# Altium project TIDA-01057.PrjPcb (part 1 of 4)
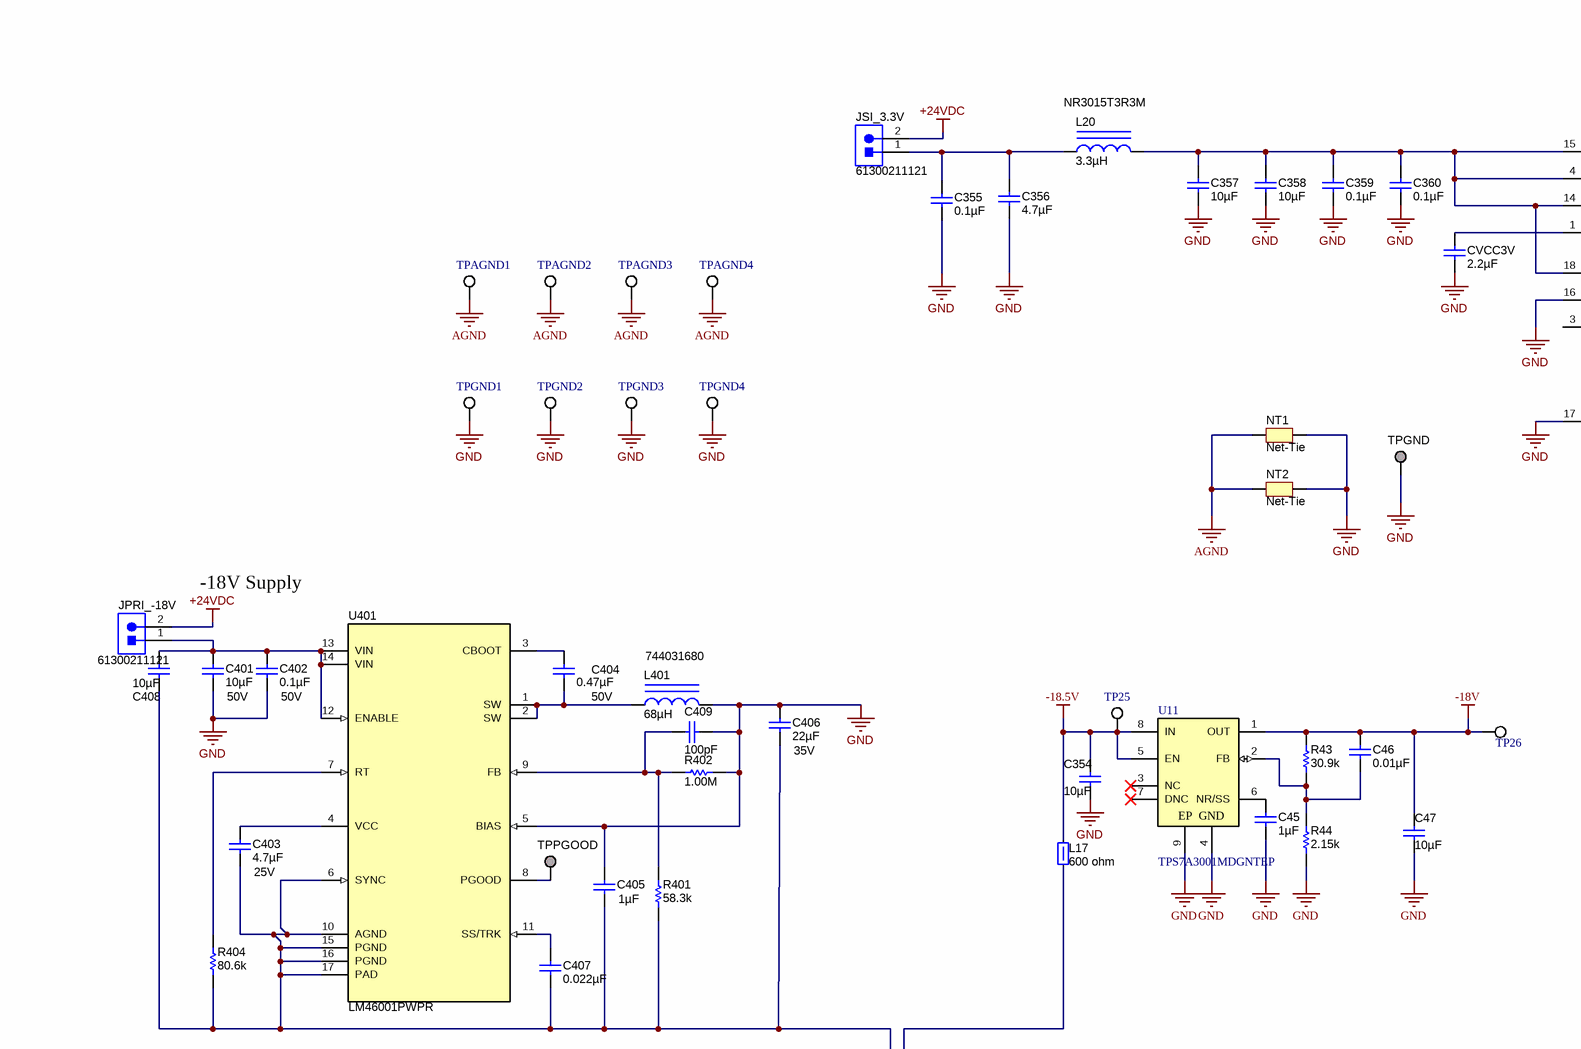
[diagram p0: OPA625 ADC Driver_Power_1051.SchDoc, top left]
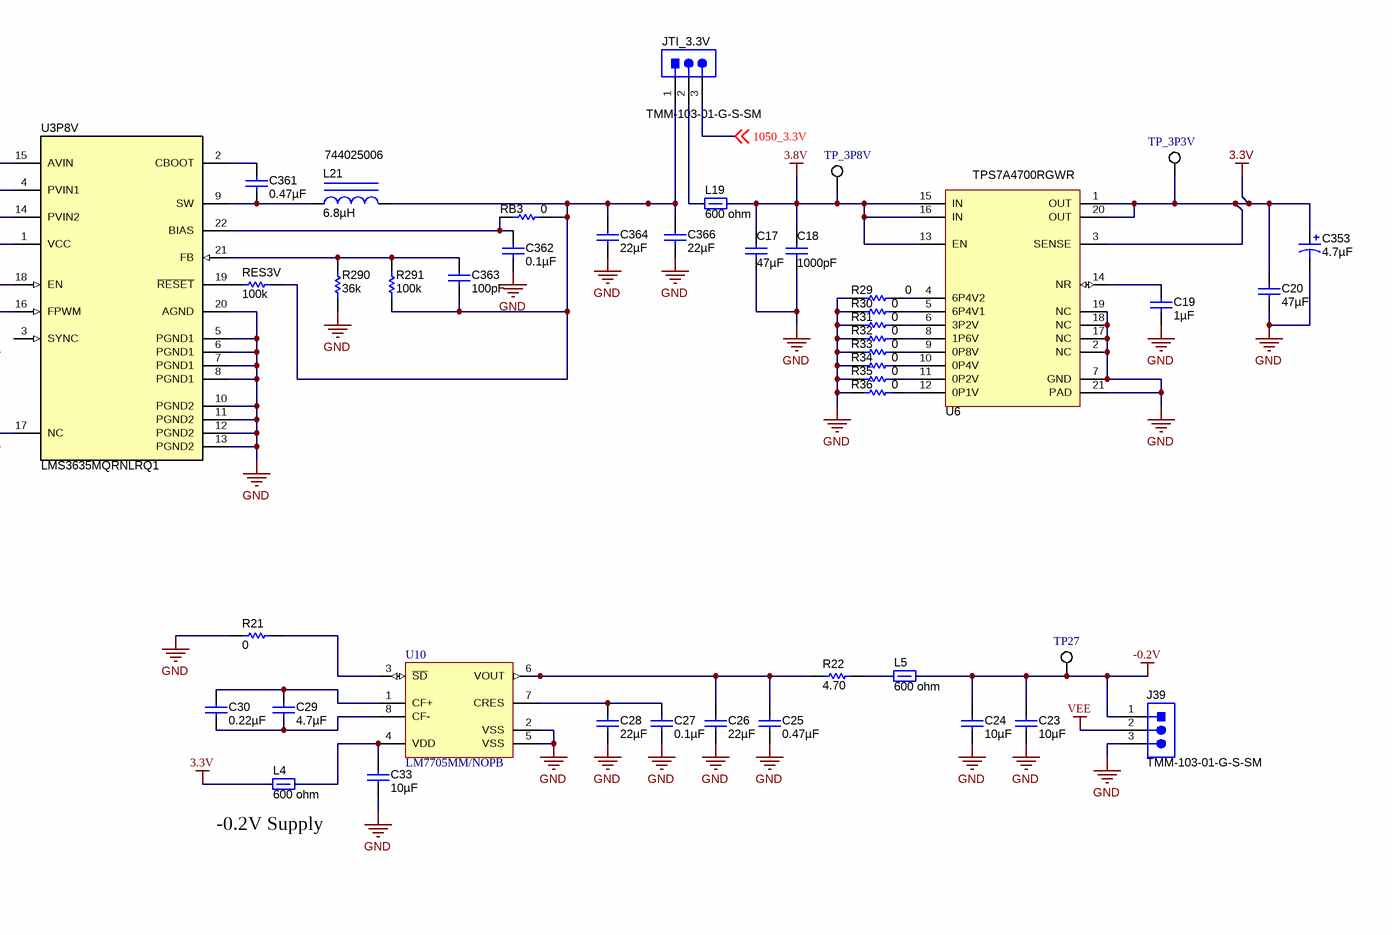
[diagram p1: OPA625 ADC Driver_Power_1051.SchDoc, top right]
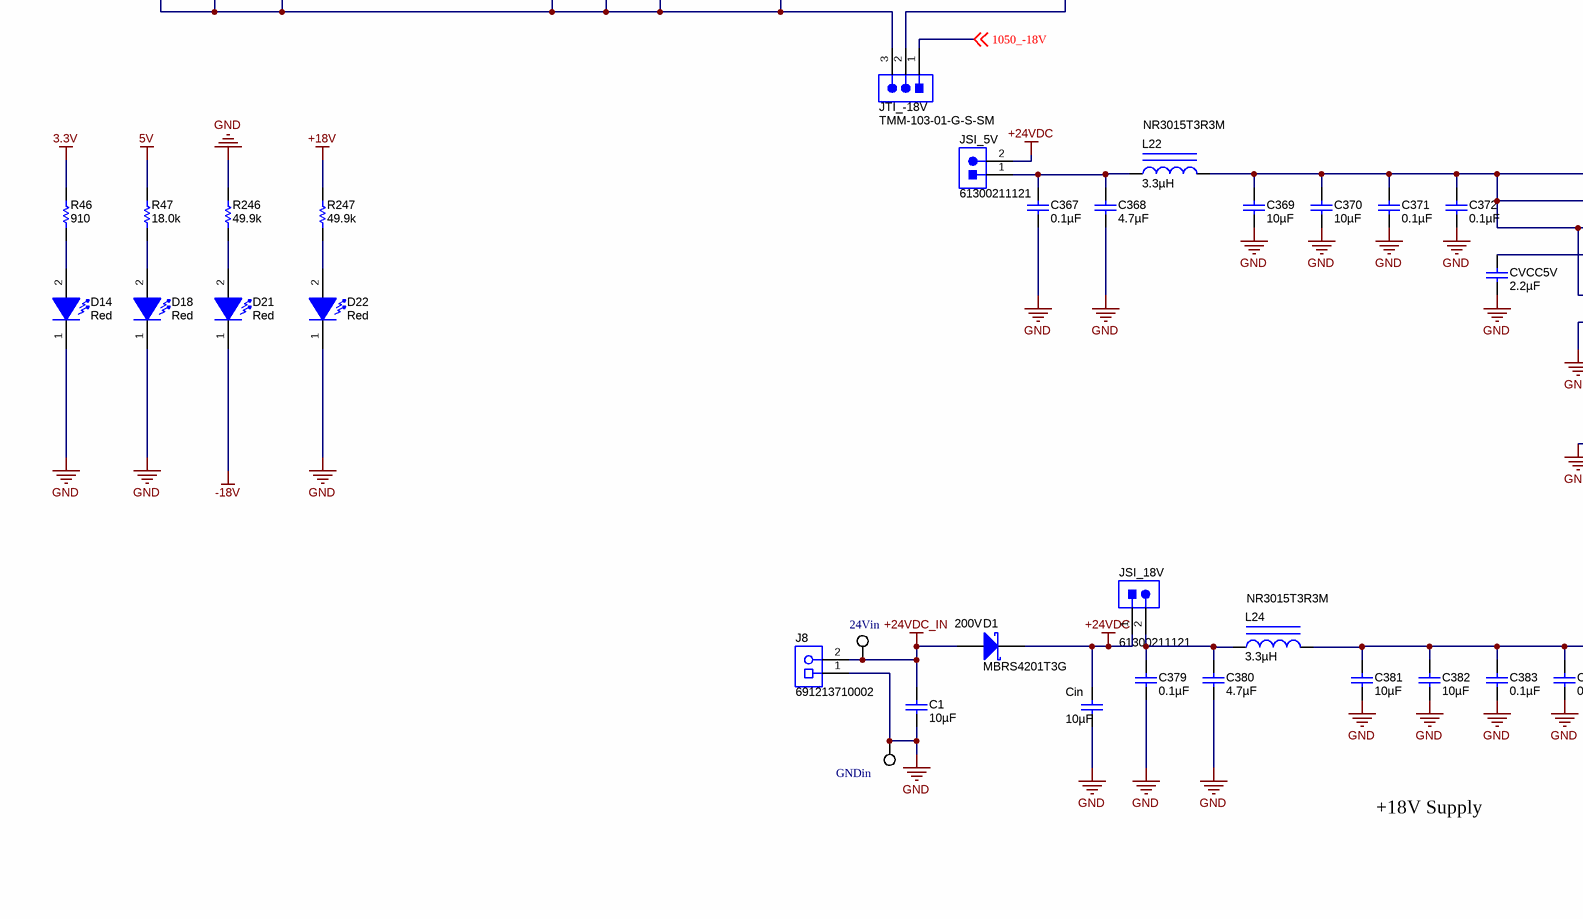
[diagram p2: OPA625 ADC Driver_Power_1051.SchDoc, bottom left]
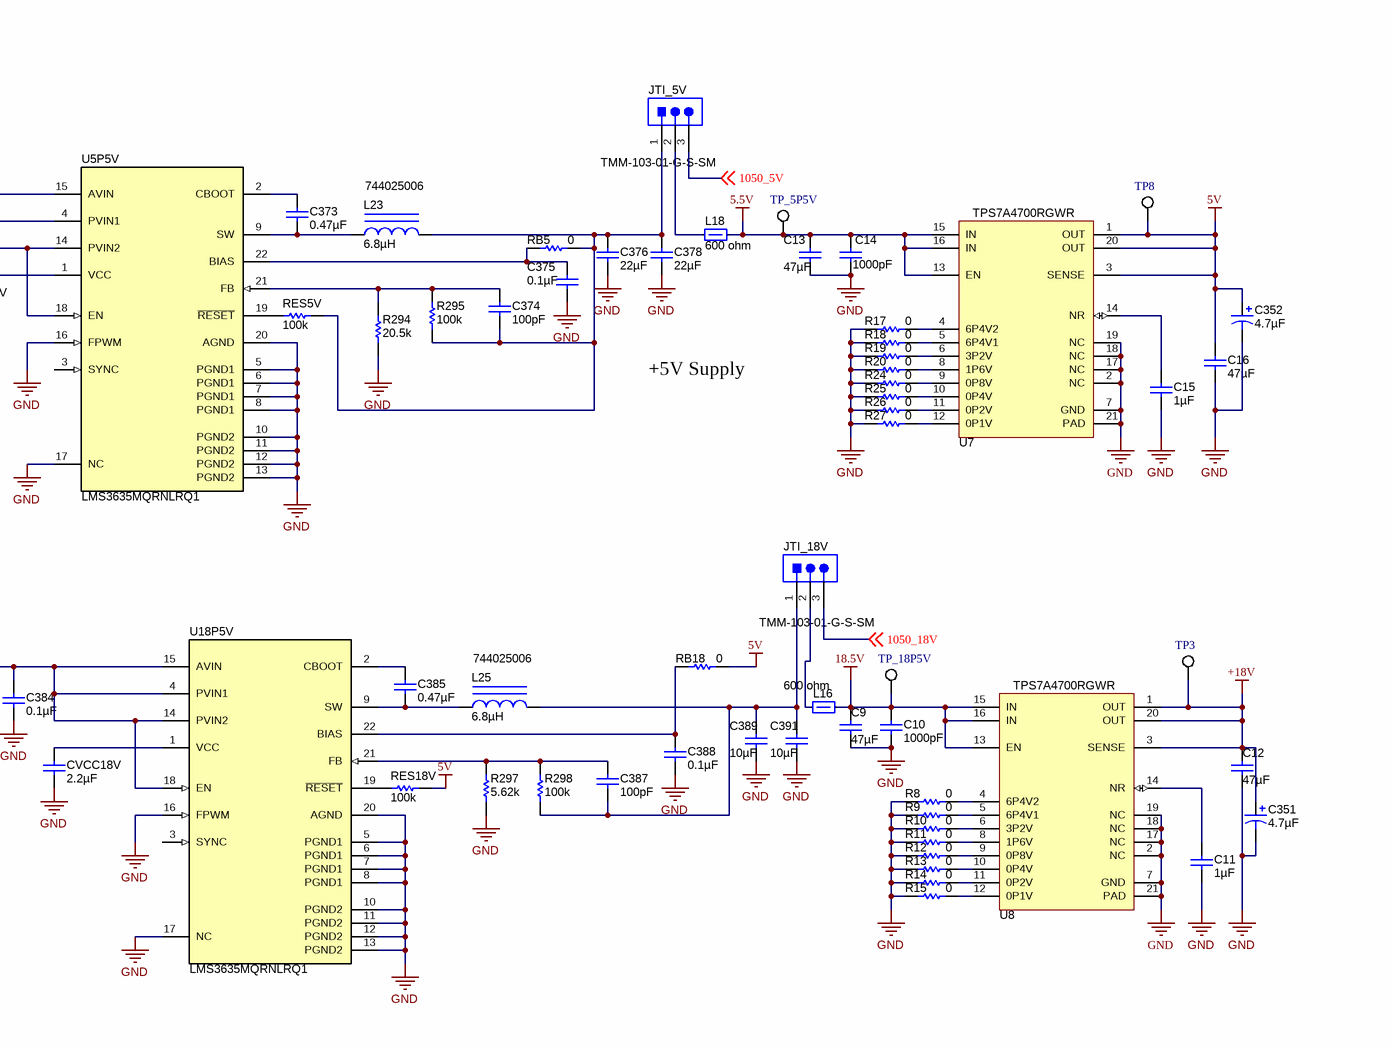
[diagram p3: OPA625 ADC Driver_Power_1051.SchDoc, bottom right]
CopyrightYear: 2017; EVM_Orderable: N/A; PCB_Layout: Dee Lim; PCB_Rev: E1; PRJ_Customer: Public Release; PRJ_Engineer: Taras Dudar & Shota Mago; PRJ_Number: TIDA-01057; PRJ_Title: OPA625 ADC Driver; SCH_Rev: E1; TechSupport: http://www.ti.com/support; TID: 01057
7 sheets, 538 parts. Net scope: global (net labels, ports and power ports of the same name join across sheets).
Board file: TIDA-01057.PcbDoc
Sheets:
  OPA625 ADC Driver_Power_1051.SchDoc
  OPA625 ADC Driver_Power_1050.SchDoc
  OPA625 ADC Driver_CoverSheet.SchDoc
  OPA625 ADC Driver_Connectors.SchDoc
  OPA625 ADC Driver_OPA625 ADC Driver REV1.0.SchDoc
  OPA625 ADC Driver_Clock.SchDoc
  OPA625 ADC Driver_Hardware.SchDoc

## Sheet OPA625 ADC Driver_Power_1051.SchDoc
size 558 x 431 mm; Date: Not shown in title block; ApprovedBy: Not shown in title block; CheckedBy: Not shown in title block; Author: Not shown in title block; CompanyName: Not shown in title block; Engineer: Not shown in title block; Organization: Not shown in title block; Address1: Not shown in title block; Address2: Not shown in title block; Address3: Not shown in title block; Address4: Not shown in title block; DocumentNumber: 2; Revision: Use project parameter SCH_Rev; SheetNumber: 2; SheetTotal: 8; PageSetup: Record=PageOptions¦CenterHorizontal=True¦CenterVertical=True¦PrintScale=0.62¦XCorrection=1.00¦YCorrection=1.00¦PrintKind=0¦BorderSize=5000000¦LeftOffset=0¦BottomOffset=0¦Orientation=2¦PaperLength=1000¦PaperWidth=1000¦Scale=100¦PaperSource=15¦PrintQuality=-3¦MediaType=1¦DitherType=10¦PrintScaleMode=1¦PaperKind=11x17¦PaperIndex=17

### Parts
24Vin  5015  [Testpoint_Keystone_Miniature]  (value not drawn)
C1  ValueDisplayed: 10µF  [1210_280]  (hidden comment: UMK325AB7106KM-T)
C9  ValueDisplayed: 47µF  [1206_190]  (hidden comment: C3216X5R1E476M160AC)
C10  ValueDisplayed: 1000pF  [0603]  (hidden comment: CGA3E2X7R2A102K080AA)
C11  ValueDisplayed: 1µF  [0805_HV]  (hidden comment: C2012X7S2A105K125AB)
C12  ValueDisplayed: 47µF  [1206_190]  (hidden comment: C3216X5R1E476M160AC)
C13  ValueDisplayed: 47µF  [1206_190]  (hidden comment: C3216X5R1E476M160AC)
C14  ValueDisplayed: 1000pF  [0603]  (hidden comment: GRM1885C1H102FA01J)
C15  ValueDisplayed: 1µF  [0603]  (hidden comment: GRM188R71E105KA12D)
C16  ValueDisplayed: 47µF  [1206_190]  (hidden comment: C3216X5R1E476M160AC)
C17  ValueDisplayed: 47µF  [1206_190]  (hidden comment: C3216X5R1E476M160AC)
C18  ValueDisplayed: 1000pF  [0603]  (hidden comment: GRM1885C1H102FA01J)
C19  ValueDisplayed: 1µF  [0603]  (hidden comment: GRM188R71E105KA12D)
C20  ValueDisplayed: 47µF  [1206_190]  (hidden comment: C3216X5R1E476M160AC)
C23  ValueDisplayed: 10µF  [0603]  (hidden comment: GRM188R61A106ME69D)
C24  ValueDisplayed: 10µF  [0603]  (hidden comment: GRM188R61A106ME69D)
C25  ValueDisplayed: 0.47µF  [0603]  (hidden comment: GRM188R71E474KA12D)
C26  ValueDisplayed: 22µF  [0603]  (hidden comment: GRM188R60J226MEA0D)
C27  ValueDisplayed: 0.1µF  [0603]  (hidden comment: GRM188R61C104KA01D)
C28  ValueDisplayed: 22µF  [0603]  (hidden comment: GRM188R60J226MEA0D)
C29  ValueDisplayed: 4.7µF  [0603]  (hidden comment: GRM188R61A475MAAJ)
C30  ValueDisplayed: 0.22µF  [0603]  (hidden comment: GRM188R61A224KA01D)
C33  ValueDisplayed: 10µF  [0603]  (hidden comment: GRM188R61A106ME69D)
C45  ValueDisplayed: 1µF  [0805_HV]  (hidden comment: C2012X7S2A105K125AB)
C46  ValueDisplayed: 0.01µF  [0603]  (hidden comment: GCM188R71H103KA37D)
C47  ValueDisplayed: 10µF  [1210_280]  (hidden comment: UMK325AB7106KM-T)
C351  ValueDisplayed: 4.7µF  [6032-28]  (hidden comment: 293D475X9025C2TE3)
C352  ValueDisplayed: 4.7µF  [6032-28]  (hidden comment: 293D475X9025C2TE3)
C353  ValueDisplayed: 4.7µF  [6032-28]  (hidden comment: 293D475X9025C2TE3)
C354  ValueDisplayed: 10µF  [1210_280]  (hidden comment: UMK325AB7106KM-T)
C355  ValueDisplayed: 0.1µF  [0805_HV]  (hidden comment: C2012X7R2A104K125AA)
C356  ValueDisplayed: 4.7µF  [1206]  (hidden comment: C3216X7R1V475K085AC)
C357  ValueDisplayed: 10µF  [1206_180]  (hidden comment: GRM31CR71E106KA12L)
C358  ValueDisplayed: 10µF  [1206_180]  (hidden comment: GRM31CR71E106KA12L)
C359  ValueDisplayed: 0.1µF  [0805_HV]  (hidden comment: C2012X7R2A104K125AA)
C360  ValueDisplayed: 0.1µF  [0805_HV]  (hidden comment: C2012X7R2A104K125AA)
C361  ValueDisplayed: 0.47µF  [0603]  (hidden comment: GCM188R71E474KA64D)
C362  ValueDisplayed: 0.1µF  [0402]  (hidden comment: C1005X6S1H104K050BB)
C363  ValueDisplayed: 100pF  [0402]  (hidden comment: C0402C101J3GACTU)
C364  ValueDisplayed: 22µF  [1210_280]  (hidden comment: CGA6P1X7R1C226M250AC)
C366  ValueDisplayed: 22µF  [1210_280]  (hidden comment: CGA6P1X7R1C226M250AC)
C367  ValueDisplayed: 0.1µF  [0805_HV]  (hidden comment: C2012X7R2A104K125AA)
C368  ValueDisplayed: 4.7µF  [1206]  (hidden comment: C3216X7R1V475K085AC)
C369  ValueDisplayed: 10µF  [1206_180]  (hidden comment: GRM31CR71E106KA12L)
C370  ValueDisplayed: 10µF  [1206_180]  (hidden comment: GRM31CR71E106KA12L)
C371  ValueDisplayed: 0.1µF  [0805_HV]  (hidden comment: C2012X7R2A104K125AA)
C372  ValueDisplayed: 0.1µF  [0805_HV]  (hidden comment: C2012X7R2A104K125AA)
C373  ValueDisplayed: 0.47µF  [0603]  (hidden comment: GCM188R71E474KA64D)
C374  ValueDisplayed: 100pF  [0402]  (hidden comment: C0402C101J3GACTU)
C375  ValueDisplayed: 0.1µF  [0402]  (hidden comment: C1005X6S1H104K050BB)
C376  ValueDisplayed: 22µF  [1210_280]  (hidden comment: CGA6P1X7R1C226M250AC)
C378  ValueDisplayed: 22µF  [1210_280]  (hidden comment: CGA6P1X7R1C226M250AC)
C379  ValueDisplayed: 0.1µF  [0805_HV]  (hidden comment: C2012X7R2A104K125AA)
C380  ValueDisplayed: 4.7µF  [1206]  (hidden comment: C3216X7R1V475K085AC)
C381  ValueDisplayed: 10µF  [1206_180]  (hidden comment: GRM31CR71E106KA12L)
C382  ValueDisplayed: 10µF  [1206_180]  (hidden comment: GRM31CR71E106KA12L)
C383  ValueDisplayed: 0.1µF  [0805_HV]  (hidden comment: C2012X7R2A104K125AA)
C384  ValueDisplayed: 0.1µF  [0805_HV]  (hidden comment: C2012X7R2A104K125AA)
C385  ValueDisplayed: 0.47µF  [0603]  (hidden comment: GCM188R71E474KA64D)
C387  ValueDisplayed: 100pF  [0402]  (hidden comment: C0402C101J3GACTU)
C388  ValueDisplayed: 0.1µF  [0402]  (hidden comment: C1005X6S1H104K050BB)
C389  ValueDisplayed: 10µF  [1210_280]  (hidden comment: UMK325AB7106KM-T)
C391  ValueDisplayed: 10µF  [1210_280]  (hidden comment: UMK325AB7106KM-T)
C401  ValueDisplayed: 10µF  Value2: 50V  [1210_280]  (hidden comment: C3225X7S1H106K250AB)
C402  ValueDisplayed: 0.1µF  Value2: 50V  [0603]  (hidden comment: C1608X5R1H104K080AA)
C403  ValueDisplayed: 4.7µF  Value2: 25V  [0603]  (hidden comment: GRM188R61E475KE11D)
C404  ValueDisplayed: 0.47µF  Value2: 50V  [0603]  (hidden comment: C1608X5R1H474K080AB)
C405  ValueDisplayed: 1µF  [0603]  (hidden comment: C1608X7R1V105K080AC)
C406  ValueDisplayed: 22µF  Value2: 35V  [1206_180]  (hidden comment: C3216X5R1V226M160AC)
C407  ValueDisplayed: 0.022µF  [0603]  (hidden comment: C0603C223K3RACTU)
C408  ValueDisplayed: 10µF  [1210_280]  (hidden comment: UMK325AB7106KM-T)
C409  ValueDisplayed: 100pF  [0603]  (hidden comment: 885012006057)
Cin  ValueDisplayed: 10µF  [1210_280]  (hidden comment: UMK325AB7106KM-T)
CVCC3V  ValueDisplayed: 2.2µF  [0603]  (hidden comment: GCM188R70J225KE22D)
CVCC5V  ValueDisplayed: 2.2µF  [0603]  (hidden comment: GCM188R70J225KE22D)
CVCC18V  ValueDisplayed: 2.2µF  [0603]  (hidden comment: GCM188R70J225KE22D)
D1  MBRS4201T3G  value 200V  [SMC]
D14  value Red  [WL-SMCW_RED]  (hidden comment: 150060RS75000)
D18  value Red  [WL-SMCW_RED]  (hidden comment: 150060RS75000)
D21  value Red  [WL-SMCW_RED]  (hidden comment: 150060RS75000)
D22  value Red  [WL-SMCW_RED]  (hidden comment: 150060RS75000)
GNDin  5015  [Testpoint_Keystone_Miniature]  (value not drawn)
J8  691213710002  [Wurth_691213710002]
J39  TMM-103-01-G-S-SM  [Samtec_TMM-103-01-x-S-SM]
JPRI_-18V  61300211121  [WURTH_61300211121]
JSI_3.3V  61300211121  [WURTH_61300211121]
JSI_5V  61300211121  [WURTH_61300211121]
JSI_18V  61300211121  [WURTH_61300211121]
JTI_3.3V  TMM-103-01-G-S-SM  [Samtec_TMM-103-01-x-S-SM]
JTI_5V  TMM-103-01-G-S-SM  [Samtec_TMM-103-01-x-S-SM]
JTI_18V  TMM-103-01-G-S-SM  [Samtec_TMM-103-01-x-S-SM]
JTI_-18V  TMM-103-01-G-S-SM  [Samtec_TMM-103-01-x-S-SM]
L4  value 600 ohm  [0805_HV]  (hidden comment: MPZ2012S601A)
L5  value 600 ohm  [0805_HV]  (hidden comment: MPZ2012S601A)
L16  value 600 ohm  [0805_HV]  (hidden comment: MPZ2012S601A)
L17  value 600 ohm  [0805_HV]  (hidden comment: MPZ2012S601A)
L18  value 600 ohm  [0805_HV]  (hidden comment: MPZ2012S601A)
L19  value 600 ohm  [0805_HV]  (hidden comment: MPZ2012S601A)
L20  NR3015T3R3M  ValueDisplayed: 3.3µH  [NR3015]
L21  744025006  ValueDisplayed: 6.8µH  [WE-TPC_2828]
L22  NR3015T3R3M  ValueDisplayed: 3.3µH  [NR3015]
L23  744025006  ValueDisplayed: 6.8µH  [WE-TPC_2828]
L24  NR3015T3R3M  ValueDisplayed: 3.3µH  [NR3015]
L25  744025006  ValueDisplayed: 6.8µH  [WE-TPC_2828]
L401  744031680  ValueDisplayed: 68µH  [WE-TPC_3816]
NT1  Net-Tie  [Net-Tie_50milWide_30milLong]  (net tie, no BOM)
NT2  Net-Tie  [Net-Tie_50milWide_30milLong]  (net tie, no BOM)
R8  ValueDisplayed: 0  [0402]  (hidden comment: ERJ-2GE0R00X)
R9  ValueDisplayed: 0  [0402]  (hidden comment: ERJ-2GE0R00X)
R10  ValueDisplayed: 0  [0402]  (hidden comment: ERJ-2GE0R00X)
R11  ValueDisplayed: 0  [0402]  (hidden comment: ERJ-2GE0R00X)
R12  ValueDisplayed: 0  [0402]  (hidden comment: ERJ-2GE0R00X)
R13  ValueDisplayed: 0  [0402]  (hidden comment: ERJ-2GE0R00X)
R14  ValueDisplayed: 0  [0402]  (hidden comment: ERJ-2GE0R00X)
R15  ValueDisplayed: 0  [0402]  (hidden comment: ERJ-2GE0R00X)
R17  ValueDisplayed: 0  [0402]  (hidden comment: ERJ-2GE0R00X)
R18  ValueDisplayed: 0  [0402]  (hidden comment: ERJ-2GE0R00X)
R19  ValueDisplayed: 0  [0402]  (hidden comment: ERJ-2GE0R00X)
R20  ValueDisplayed: 0  [0402]  (hidden comment: ERJ-2GE0R00X)
R21  ValueDisplayed: 0  [0603]  (hidden comment: CRCW06030000Z0EA)
R22  ValueDisplayed: 4.70  [0603]  (hidden comment: RT0603DRE074R7L)
R24  ValueDisplayed: 0  [0402]  (hidden comment: ERJ-2GE0R00X)
R25  ValueDisplayed: 0  [0402]  (hidden comment: ERJ-2GE0R00X)
R26  ValueDisplayed: 0  [0402]  (hidden comment: ERJ-2GE0R00X)
R27  ValueDisplayed: 0  [0402]  (hidden comment: ERJ-2GE0R00X)
R29  ValueDisplayed: 0  [0402]  (hidden comment: ERJ-2GE0R00X)
R30  ValueDisplayed: 0  [0402]  (hidden comment: ERJ-2GE0R00X)
R31  ValueDisplayed: 0  [0402]  (hidden comment: ERJ-2GE0R00X)
R32  ValueDisplayed: 0  [0402]  (hidden comment: ERJ-2GE0R00X)
R33  ValueDisplayed: 0  [0402]  (hidden comment: ERJ-2GE0R00X)
R34  ValueDisplayed: 0  [0402]  (hidden comment: ERJ-2GE0R00X)
R35  ValueDisplayed: 0  [0402]  (hidden comment: ERJ-2GE0R00X)
R36  ValueDisplayed: 0  [0402]  (hidden comment: ERJ-2GE0R00X)
R43  ValueDisplayed: 30.9k  [0603]  (hidden comment: RG1608P-3092-B-T5)
R44  ValueDisplayed: 2.15k  [0603]  (hidden comment: RT0603BRD072K15L)
R46  ValueDisplayed: 910  [0603]  (hidden comment: RC0603JR-07910RL)
R47  ValueDisplayed: 18.0k  [0603]  (hidden comment: RT0603BRD0718KL)
R246  ValueDisplayed: 49.9k  [0603]  (hidden comment: RG1608P-4992-B-T5)
R247  ValueDisplayed: 49.9k  [0603]  (hidden comment: RG1608P-4992-B-T5)
R290  ValueDisplayed: 36k  [0402]  (hidden comment: CRCW040236K0JNED)
R291  ValueDisplayed: 100k  [0402]  (hidden comment: CRCW0402100KFKED)
R294  ValueDisplayed: 20.5k  [0402]  (hidden comment: CRCW040222K6FKED)
R295  ValueDisplayed: 100k  [0402]  (hidden comment: CRCW0402100KFKED)
R297  ValueDisplayed: 5.62k  [0402]  (hidden comment: PCF0402-12-5K62BT1)
R298  ValueDisplayed: 100k  [0402]  (hidden comment: CRCW0402100KFKED)
R401  ValueDisplayed: 58.3k  [0603]  (hidden comment: RT0603BRD0758K3L)
R402  ValueDisplayed: 1.00M  [0603]  (hidden comment: RC0603FR-071ML)
R404  ValueDisplayed: 80.6k  [0603]  (hidden comment: CRCW060380K6FKEA)
RB3  ValueDisplayed: 0  [0402]  (hidden comment: ERJ-2GE0R00X)
RB5  ValueDisplayed: 0  [0402]  (hidden comment: ERJ-2GE0R00X)
RB18  ValueDisplayed: 0  [0402]  (hidden comment: ERJ-2GE0R00X)
RES3V  ValueDisplayed: 100k  [0603]  (hidden comment: RG1608P-104-B-T5)
RES5V  ValueDisplayed: 100k  [0603]  (hidden comment: RG1608P-104-B-T5)
RES18V  ValueDisplayed: 100k  [0603]  (hidden comment: RG1608P-104-B-T5)
TP3  5015  [Testpoint_Keystone_Miniature]  (value not drawn)
TP8  5015  [Testpoint_Keystone_Miniature]  (value not drawn)
TP25  5015  [Testpoint_Keystone_Miniature]  (value not drawn)
TP26  5015  [Testpoint_Keystone_Miniature]  (value not drawn)
TP27  5015  [Testpoint_Keystone_Miniature]  (value not drawn)
TP_3P3V  5015  [Testpoint_Keystone_Miniature]  (value not drawn)
TP_3P8V  5015  [Testpoint_Keystone_Miniature]  (value not drawn)
TP_5P5V  5015  [Testpoint_Keystone_Miniature]  (value not drawn)
TP_18P5V  5015  [Testpoint_Keystone_Miniature]  (value not drawn)
TPAGND1  5015  [Testpoint_Keystone_Miniature]  (value not drawn)
TPAGND2  5015  [Testpoint_Keystone_Miniature]  (value not drawn)
TPAGND3  5015  [Testpoint_Keystone_Miniature]  (value not drawn)
TPAGND4  5015  [Testpoint_Keystone_Miniature]  (value not drawn)
TPGND  Pogo Pad  [PogoPad]  (value not drawn)  (no BOM)
TPGND1  5015  [Testpoint_Keystone_Miniature]  (value not drawn)
TPGND2  5015  [Testpoint_Keystone_Miniature]  (value not drawn)
TPGND3  5015  [Testpoint_Keystone_Miniature]  (value not drawn)
TPGND4  5015  [Testpoint_Keystone_Miniature]  (value not drawn)
TPPGOOD  Pogo Pad  [PogoPad]  (value not drawn)  (no BOM)
U3P8V  LMS3635MQRNLRQ1  [RNL0022A_NV]
U5P5V  LMS3635MQRNLRQ1  [RNL0022A_NV]
U6  TPS7A4700RGWR  [RGW0020A]
U7  TPS7A4700RGWR  [RGW0020A]
U8  TPS7A4700RGWR  [RGW0020A]
U10  LM7705MM/NOPB  [MUA08A_N]
U11  TPS7A3001MDGNTEP  [DGN0008D_N]
U18P5V  LMS3635MQRNLRQ1  [RNL0022A_NV]
U401  LM46001PWPR  [PWP0016G_N]

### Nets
3.3V: C20.1 C353.1(+) L4.2 R46.2 TP_3P3V.1 U6.1(OUT) U6.3(SENSE) U6.20(OUT)
3.8V: C17.1 C18.1 L19.2 TP_3P8V.1 U6.13(EN) U6.15(IN) U6.16(IN)
5.5V: C13.1 C14.1 L18.2 TP_5P5V.1 U7.13(EN) U7.15(IN) U7.16(IN)
5V: C16.1 C352.1(+) R47.2 RB18.2 RES18V.1 TP8.1 U7.1(OUT) U7.3(SENSE) U7.20(OUT)
18.5V: C9.1 C10.1 L16.1 TP_18P5V.1 U8.13(EN) U8.15(IN) U8.16(IN)
+18V: C12.1 C351.1(+) R247.2 TP3.1 U8.1(OUT) U8.3(SENSE) U8.20(OUT)
+24VDC: Cin.1 D1.1(K) JPRI_-18V.2 JSI_3.3V.2 JSI_5V.2 JSI_18V.1
+24VDC_IN: 24Vin.1 C1.1 D1.2(A) J8.2
-0.2V: C23.1 C24.1 J39.1 L5.1 TP27.1
-18.5V: C354.1 L17.1 TP25.1 U11.5(EN) U11.8(IN)
-18V: C46.1 C47.1 D21.1(K) R43.2 TP26.1 U11.1(OUT)
AGND: NT1.1 NT2.1 TPAGND1.1 TPAGND2.1 TPAGND3.1 TPAGND4.1
GND: C1.2 C9.2 C10.2 C11.2 C12.2 C13.2 C14.2 C15.1 C16.2 C17.2 C18.2 C19.1 C20.2 C23.2 C24.2 C25.2 C26.2 C27.2 C28.2 C33.2 C45.2 C47.2 C351.2(-) C352.2(-) C353.2(-) C354.2 C355.2 C356.2 C357.2 C358.2 C359.2 C360.2 C362.2 C364.2 C366.2 C367.2 C368.2 C369.2 C370.2 C371.2 C372.2 C375.2 C376.2 C378.2 C379.2 C380.2 C381.2 C382.2 C383.2 C384.2 C388.2 C389.2 C391.2 C401.2 C402.2 C405.1 C406.1 C409.1 Cin.2 CVCC3V.2 CVCC5V.2 CVCC18V.2 D14.1(K) D18.1(K) D22.1(K) GNDin.1 J8.1 J39.3 L401.2 NT1.2 NT2.2 R8.1 R9.1 R10.1 R11.1 R12.1 R13.1 R14.1 R15.1 R17.1 R18.1 R19.1 R20.1 R21.1 R24.1 R25.1 R26.1 R27.1 R29.1 R30.1 R31.1 R32.1 R33.1 R34.1 R35.1 R36.1 R44.1 R246.2 R290.1 R294.1 R297.1 R402.2 TPGND.1 TPGND1.1 TPGND2.1 TPGND3.1 TPGND4.1 U3P8V.5(PGND1) U3P8V.6(PGND1) U3P8V.7(PGND1) U3P8V.8(PGND1) U3P8V.10(PGND2) U3P8V.11(PGND2) U3P8V.12(PGND2) U3P8V.13(PGND2) U3P8V.16(FPWM) U3P8V.17(NC) U3P8V.20(AGND) U5P5V.5(PGND1) U5P5V.6(PGND1) U5P5V.7(PGND1) U5P5V.8(PGND1) U5P5V.10(PGND2) U5P5V.11(PGND2) U5P5V.12(PGND2) U5P5V.13(PGND2) U5P5V.16(FPWM) U5P5V.17(NC) U5P5V.20(AGND) U6.2(NC) U6.7(GND) U6.17(NC) U6.18(NC) U6.19(NC) U6.21(PAD) U7.2(NC) U7.7(GND) U7.17(NC) U7.18(NC) U7.19(NC) U7.21(PAD) U8.2(NC) U8.7(GND) U8.17(NC) U8.18(NC) U8.19(NC) U8.21(PAD) U10.2(VSS) U10.5(VSS) U11.4(GND) U11.9(EP) U18P5V.5(PGND1) U18P5V.6(PGND1) U18P5V.7(PGND1) U18P5V.8(PGND1) U18P5V.10(PGND2) U18P5V.11(PGND2) U18P5V.12(PGND2) U18P5V.13(PGND2) U18P5V.16(FPWM) U18P5V.17(NC) U18P5V.20(AGND) U401.5(BIAS)
VEE: J39.2
1050_3.3V: JTI_3.3V.3 ; off-sheet 1050_3.3V
1050_5V: JTI_5V.3 ; off-sheet 1050_5V
1050_18V: JTI_18V.3 ; off-sheet 1050_18V
1050_-18V: JTI_-18V.1 ; off-sheet 1050_-18V
NetC11_1: C11.1 U8.14(NR)
NetC15_2: C15.2 U7.14(NR)
NetC19_2: C19.2 U6.14(NR)
NetC25_1: C25.1 C26.1 R22.1 U10.6(VOUT)
NetC27_1: C27.1 C28.1 U10.7(CRES)
NetC29_1: C29.1 C30.1 U10.1(CF+)
NetC29_2: C29.2 C30.2 U10.8(CF-)
NetC33_1: C33.1 L4.1 U10.4(VDD)
NetC45_1: C45.1 U11.6(NR/SS)
NetC46_2: C46.2 R43.1 R44.2 U11.2(FB)
NetC355_1: C355.1 C356.1 JSI_3.3V.1 L20.1
NetC357_1: C357.1 C358.1 C359.1 C360.1 L20.2 U3P8V.4(PVIN1) U3P8V.14(PVIN2) U3P8V.15(AVIN) U3P8V.18(EN)
NetC361_1: C361.1 U3P8V.2(CBOOT)
NetC361_2: C361.2 L21.1 U3P8V.9(SW)
NetC362_1: C362.1 RB3.1 U3P8V.22(BIAS)
NetC363_1: C363.1 R290.2 R291.2 U3P8V.21(FB)
NetC363_2: C363.2 C364.1 C366.1 JTI_3.3V.1 L21.2 R291.1 RB3.2 RES3V.1
NetC367_1: C367.1 C368.1 JSI_5V.1 L22.1
NetC369_1: C369.1 C370.1 C371.1 C372.1 L22.2 U5P5V.4(PVIN1) U5P5V.14(PVIN2) U5P5V.15(AVIN) U5P5V.18(EN)
NetC373_1: C373.1 U5P5V.2(CBOOT)
NetC373_2: C373.2 L23.1 U5P5V.9(SW)
NetC374_1: C374.1 R294.2 R295.2 U5P5V.21(FB)
NetC374_2: C374.2 C376.1 C378.1 JTI_5V.1 L23.2 R295.1 RB5.2 RES5V.1
NetC375_1: C375.1 RB5.1 U5P5V.22(BIAS)
NetC379_1: C379.1 C380.1 JSI_18V.2 L24.1
NetC381_1: C381.1 C382.1 C383.1 C384.1 L24.2 U18P5V.4(PVIN1) U18P5V.14(PVIN2) U18P5V.15(AVIN) U18P5V.18(EN)
NetC385_1: C385.1 U18P5V.2(CBOOT)
NetC385_2: C385.2 L25.1 U18P5V.9(SW)
NetC387_1: C387.1 R297.2 R298.2 U18P5V.21(FB)
NetC387_2: C387.2 C389.1 C391.1 JTI_18V.1 L25.2 R298.1
NetC388_1: C388.1 RB18.1 U18P5V.22(BIAS)
NetC401_1: C401.1 C402.1 C408.1 JPRI_-18V.1 U401.12(ENABLE) U401.13(VIN) U401.14(VIN)
NetC403_1: C403.1 U401.4(VCC)
NetC403_2: C403.2 C405.2 C406.2 C407.2 C408.2 JTI_-18V.3 R401.1 R404.1 U401.6(SYNC) U401.10(AGND) U401.15(PGND) U401.16(PGND) U401.17(PAD)
NetC404_1: C404.1 U401.3(CBOOT)
NetC404_2: C404.2 L401.1 U401.1(SW) U401.2(SW)
NetC407_1: C407.1 U401.11(SS/TRK)
NetC409_2: C409.2 R401.2 R402.1 U401.9(FB)
NetCVCC3V_1: CVCC3V.1 U3P8V.1(VCC)
NetCVCC5V_1: CVCC5V.1 U5P5V.1(VCC)
NetCVCC18V_1: CVCC18V.1 U18P5V.1(VCC)
NetD14_2: D14.2(A) R46.1
NetD18_2: D18.2(A) R47.1
NetD21_2: D21.2(A) R246.1
NetD22_2: D22.2(A) R247.1
NetJTI_3.3V_2: JTI_3.3V.2 L19.1
NetJTI_5V_2: JTI_5V.2 L18.1
NetJTI_18V_2: JTI_18V.2 L16.2
NetJTI_-18V_2: JTI_-18V.2 L17.2
NetL5_2: L5.2 R22.2
NetR8_2: R8.2 U8.4(6P4V2)
NetR9_2: R9.2 U8.5(6P4V1)
NetR10_2: R10.2 U8.6(3P2V)
NetR11_2: R11.2 U8.8(1P6V)
NetR12_2: R12.2 U8.9(0P8V)
NetR13_2: R13.2 U8.10(0P4V)
NetR14_2: R14.2 U8.11(0P2V)
NetR15_2: R15.2 U8.12(0P1V)
NetR17_2: R17.2 U7.4(6P4V2)
NetR18_2: R18.2 U7.5(6P4V1)
NetR19_2: R19.2 U7.6(3P2V)
NetR20_2: R20.2 U7.8(1P6V)
NetR21_2: R21.2 U10.3(~{SD})
NetR24_2: R24.2 U7.9(0P8V)
NetR25_2: R25.2 U7.10(0P4V)
NetR26_2: R26.2 U7.11(0P2V)
NetR27_2: R27.2 U7.12(0P1V)
NetR29_2: R29.2 U6.4(6P4V2)
NetR30_2: R30.2 U6.5(6P4V1)
NetR31_2: R31.2 U6.6(3P2V)
NetR32_2: R32.2 U6.8(1P6V)
NetR33_2: R33.2 U6.9(0P8V)
NetR34_2: R34.2 U6.10(0P4V)
NetR35_2: R35.2 U6.11(0P2V)
NetR36_2: R36.2 U6.12(0P1V)
NetR404_2: R404.2 U401.7(RT)
NetRES3V_2: RES3V.2 U3P8V.19(~{RESET})
NetRES5V_2: RES5V.2 U5P5V.19(~{RESET})
NetRES18V_2: RES18V.2 U18P5V.19(~{RESET})
NetTPPGOOD_1: TPPGOOD.1 U401.8(PGOOD)

Not connected (* = marked no-connect by the designer): U3P8V 3(SYNC); U5P5V 3(SYNC); U11 3(NC)* 7(DNC)*; U18P5V 3(SYNC)

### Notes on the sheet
- -18V Supply
- (near L4) -0.2V Supply
- +5V Supply
- +18V Supply

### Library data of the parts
24Vin GNDin TP3 TP8 TP25-TP27 TP_3P3V TP_3P8V TP_5P5V TP_18P5V TPAGND1-TPAGND4 TPGND1-TPGND4 = 5015: Test Point, Miniature, SMT; Manufacturer: Keystone; CompType: Test Point Loop
C1 = UMK325AB7106KM-T: CAP, CERM, 10 µF, 50 V, +/- 10%, X7R, 1210; Manufacturer: Taiyo Yuden; Polarized: N; CompType: Capacitor; Value: 10uF; U/M: EA; Cap_F: 0.00001; Tolerance_%: 10; Value1: Unknown; VDC_V: 50; Value2: 50V; TaMin_C: -55; TaMax_C: 125; Cap_Case: 1210; SizeArea_mm2: 8; SizeAreaWB_mm2: 14.7; SizeX_mm: 3.2; SizeY_mm: 2.5; SizeZ_mm: 2.8; AEC Category: Q200
C9 C12 C13 C16 C17 C20 = C3216X5R1E476M160AC: CAP, CERM, 47 µF, 25 V, +/- 20%, X5R, 1206_190; Manufacturer: TDK; Polarized: N; CompType: Capacitor; Value: 47uF; U/M: EA; Cap_F: 0.000047; Tolerance_%: 20; Value1: Unknown; VDC_V: 25; Value2: 25V; TaMin_C: -55; TaMax_C: 85; Cap_Case: 1206; AEC Category: Q200
C10 = CGA3E2X7R2A102K080AA: CAP, CERM, 1000 pF, 100 V, +/- 10%, X7R, AEC-Q200 Grade 1, 0603; Manufacturer: TDK; Polarized: N; CompType: Capacitor; Value: 1000pF; U/M: EA; Cap_F: 0.000000001; Tolerance_%: 10; ESR_ohm: 1.97137; Value1: 1.97137 ohm; VDC_V: 100; Value2: 100V; IRMS_A: 0.305705; TaMin_C: -55; TaMax_C: 125; SizeArea_mm2: 1.28; SizeAreaWB_mm2: 4.68; SizeX_mm: 1.6; SizeY_mm: 0.8; SizeZ_mm: 1; AEC Category: Q200; AEC Qualified: Y
C11 C45 = C2012X7S2A105K125AB: CAP, CERM, 1 µF, 100 V, +/- 10%, X7S, 0805; Manufacturer: TDK; Polarized: N; CompType: Capacitor; Value: 1uF; U/M: EA; Cap_F: 0.000001; Tolerance_%: 10; ESR_ohm: 0.008255; Value1: 0.008255 ohm; VDC_V: 100; Value2: 100V; IRMS_A: 2.27442; TaMin_C: -55; TaMax_C: 125; Cap_Case: 0805; SizeArea_mm2: 2.5; SizeAreaWB_mm2: 6.75; SizeX_mm: 2; SizeY_mm: 1.25; SizeZ_mm: 1.45; AEC Category: Q200
C14 C18 = GRM1885C1H102FA01J: CAP, CERM, 1000 pF, 50 V, +/- 1%, C0G/NP0, 0603; Manufacturer: MuRata; Polarized: N; CompType: Capacitor; Value: 1000pF; U/M: EA; Cap_F: 0.000000001; Tolerance_%: 1; Value1: Unknown; VDC_V: 50; Value2: 50V; TaMin_C: -55; TaMax_C: 125; AEC Category: Q200
C15 C19 = GRM188R71E105KA12D: CAP, CERM, 1 µF, 25 V, +/- 10%, X7R, 0603; Manufacturer: MuRata; Polarized: N; CompType: Capacitor; Value: 1uF; U/M: EA; Cap_F: 0.000001; Tolerance_%: 10; Value1: Unknown; VDC_V: 25; Value2: 25V; TaMin_C: -55; TaMax_C: 125; AEC Category: Q200
C23 C24 C33 = GRM188R61A106ME69D: CAP, CERM, 10 µF, 10 V, +/- 20%, X5R, 0603; Manufacturer: MuRata; Polarized: N; CompType: Capacitor; Value: 10uF; U/M: EA; Cap_F: 0.00001; Tolerance_%: 20; Value1: Unknown; VDC_V: 10; Value2: 10V; TaMin_C: -55; TaMax_C: 85; SizeArea_mm2: 1.28; SizeAreaWB_mm2: 4.68; SizeX_mm: 1.6; SizeY_mm: 0.8; SizeZ_mm: 1; AEC Category: Q200
C25 = GRM188R71E474KA12D: CAP, CERM, 0.47 µF, 25 V, +/- 10%, X7R, 0603; Manufacturer: MuRata; Polarized: N; CompType: Capacitor; Value: 0.47uF; U/M: EA; Cap_F: 0.00000047; Tolerance_%: 10; Value1: Unknown; VDC_V: 25; Value2: 25V; TaMin_C: -55; TaMax_C: 125; SizeArea_mm2: 1.28; SizeAreaWB_mm2: 4.68; SizeX_mm: 1.6; SizeY_mm: 0.8; SizeZ_mm: 1; AEC Category: Q200
C26 C28 = GRM188R60J226MEA0D: CAP, CERM, 22 µF, 6.3 V, +/- 20%, X5R, 0603; Manufacturer: MuRata; Polarized: N; CompType: Capacitor; Value: 22uF; U/M: EA; Cap_F: 0.000022; Tolerance_%: 20; Value1: Unknown; VDC_V: 6.3; Value2: 6.3V; TaMin_C: -55; TaMax_C: 85; SizeArea_mm2: 1.28; SizeAreaWB_mm2: 4.68; SizeX_mm: 1.6; SizeY_mm: 0.8; SizeZ_mm: 1; AEC Category: Q200
C27 = GRM188R61C104KA01D: CAP, CERM, 0.1 µF, 16 V, +/- 10%, X5R, 0603; Manufacturer: MuRata; Polarized: N; CompType: Capacitor; Value: 0.1uF; U/M: EA; Cap_F: 0.0000001; Tolerance_%: 10; Value1: Unknown; VDC_V: 16; Value2: 16V; TaMin_C: -55; TaMax_C: 85; SizeArea_mm2: 1.28; SizeAreaWB_mm2: 4.68; SizeX_mm: 1.6; SizeY_mm: 0.8; SizeZ_mm: 1; AEC Category: Q200
C29 = GRM188R61A475MAAJ: CAP, CERM, 4.7 µF, 10 V, +/- 20%, X5R, 0603; Manufacturer: MuRata; Polarized: N; CompType: Capacitor; Value: 4.7uF; U/M: EA; Cap_F: 0.0000047; Tolerance_%: 20; Value1: Unknown; VDC_V: 10; Value2: 10V; TaMin_C: -55; TaMax_C: 85; SizeArea_mm2: 1.28; SizeAreaWB_mm2: 4.68; SizeX_mm: 1.6; SizeY_mm: 0.8; SizeZ_mm: 1; AEC Category: Q200
C30 = GRM188R61A224KA01D: CAP, CERM, 0.22 µF, 10 V, +/- 10%, X5R, 0603; Manufacturer: MuRata; Polarized: N; CompType: Capacitor; Value: 0.22uF; U/M: EA; Cap_F: 0.00000022; Tolerance_%: 10; Value1: Unknown; Value2: 10V; TaMin_C: -55; TaMax_C: 85; SizeArea_mm2: 1.28; SizeAreaWB_mm2: 4.68; SizeX_mm: 1.6; SizeY_mm: 0.8; SizeZ_mm: 1; AEC Category: Q200
C46 = GCM188R71H103KA37D: CAP, CERM, 0.01 µF, 50 V, +/- 10%, X7R, AEC-Q200 Grade 1, 0603; Manufacturer: MuRata; Polarized: N; CompType: Capacitor; Value: 0.01uF; U/M: EA; Cap_F: 0.00000001; Tolerance_%: 10; Value1: Unknown; VDC_V: 50; Value2: 50V; TaMin_C: -55; TaMax_C: 125; SizeArea_mm2: 1.28; SizeAreaWB_mm2: 4.68; SizeX_mm: 1.6; SizeY_mm: 0.8; SizeZ_mm: 1; AEC Category: Q200; AEC Qualified: Y
C47 C354 C389 C391 C408 Cin = UMK325AB7106KM-T: CAP, CERM, 10 µF, 50 V, +/- 10%, X7R, 1210; Manufacturer: Taiyo Yuden; Polarized: N; CompType: Capacitor; Value: 10uF; U/M: EA; Cap_F: 0.00001; Tolerance_%: 10; Value1: Unknown; VDC_V: 50; Value2: 50V; TaMin_C: -55; TaMax_C: 125; Cap_Case: 1210; AEC Category: Q200
C351-C353 = 293D475X9025C2TE3: CAP, TA, 4.7 µF, 25 V, +/- 10%, 2 ohm, SMD; Manufacturer: Vishay-Sprague; Polarized: Y; CompType: Capacitor; Value: 4.7uF; U/M: EA; Cap_F: 0.0000047; Tolerance_%: 10; Value1: 2 ohm; VDC_V: 25; Value2: 25V; ESR_ohm: 2; IRMS_A: 0.24; TaMin_C: -55; TaMax_C: 125; Cap_Case: C; SizeAreaWB_mm2: 41.6; SizeArea_mm2: 19.2; SizeX_mm: 6; SizeY_mm: 3.2; SizeZ_mm: 2.8; AEC Category: Q200
C355 C359 C360 C367 C371 C372 C379 C383 C384 = C2012X7R2A104K125AA: CAP, CERM, 0.1 µF, 100 V, +/- 10%, X7R, 0805; Manufacturer: TDK; Polarized: N; CompType: Capacitor; Value: 0.1uF; U/M: EA; Cap_F: 0.0000001; Tolerance_%: 10; ESR_ohm: 0.020726; Value1: 0.020726 ohm; VDC_V: 100; Value2: 100V; IRMS_A: 1.456; TaMin_C: -55; TaMax_C: 125; Cap_Case: 0805; SizeArea_mm2: 2.5; SizeAreaWB_mm2: 6.75; SizeX_mm: 2; SizeY_mm: 1.25; SizeZ_mm: 1.45; AEC Category: Q200
C356 C368 C380 = C3216X7R1V475K085AC: CAP, CERM, 4.7 µF, 35 V, +/- 10%, X7R, 1206; Manufacturer: TDK; Polarized: N; CompType: Capacitor; Value: 4.7uF; U/M: EA; Cap_F: 0.0000047; Tolerance_%: 10; ESR_ohm: 0.003785; Value1: 0.003785 ohm; VDC_V: 35; Value2: 35V; IRMS_A: 3.73011; TaMin_C: -55; TaMax_C: 125; SizeArea_mm2: 5.12; SizeAreaWB_mm2: 10.92; SizeX_mm: 3.2; SizeY_mm: 1.6; SizeZ_mm: 1.35; AEC Category: Q200
C357 C358 C369 C370 C381 C382 = GRM31CR71E106KA12L: CAP, CERM, 10 µF, 25 V, +/- 10%, X7R, 1206; Manufacturer: MuRata; Polarized: N; CompType: Capacitor; Value: 10uF; U/M: EA; Cap_F: 0.00001; Tolerance_%: 10; Value1: Unknown; VDC_V: 25; Value2: 25V; TaMin_C: -55; TaMax_C: 125; Cap_Case: 2220; SizeArea_mm2: 5.12; SizeAreaWB_mm2: 10.92; SizeX_mm: 3.2; SizeY_mm: 1.6; SizeZ_mm: 1.8; AEC Category: Q200
C361 C373 C385 = GCM188R71E474KA64D: CAP, CERM, 0.47 µF, 25 V, +/- 10%, X7R, AEC-Q200 Grade 1, 0603; Manufacturer: MuRata; Polarized: N; CompType: Capacitor; Value: 0.47uF; U/M: EA; Cap_F: 0.00000047; Tolerance_%: 10; Value1: Unknown; VDC_V: 25; Value2: 25V; TaMin_C: -55; TaMax_C: 125; SizeArea_mm2: 1.28; SizeAreaWB_mm2: 4.68; SizeX_mm: 1.6; SizeY_mm: 0.8; SizeZ_mm: 1; AEC Category: Q200; AEC Qualified: Y
C362 C375 C388 = C1005X6S1H104K050BB: CAP, CERM, 0.1 µF, 50 V, +/- 10%, X6S, 0402; Manufacturer: TDK; Polarized: N; CompType: Capacitor; Value: 0.1uF; U/M: EA; Cap_F: 0.0000001; Tolerance_%: 10; ESR_ohm: 0.039064; Value1: 0.039064 ohm; VDC_V: 50; Value2: 50V; IRMS_A: 0.814669; TaMin_C: -55; TaMax_C: 105; SizeArea_mm2: 0.5; SizeAreaWB_mm2: 3; SizeX_mm: 1; SizeZ_mm: 0.6; AEC Category: Q200
C363 C374 C387 = C0402C101J3GACTU: CAP, CERM, 100 pF, 25 V, +/- 5%, C0G/NP0, 0402; Manufacturer: Kemet; Polarized: N; CompType: Capacitor; Value: 100pF; U/M: EA; Cap_F: 0.0000000001; Tolerance_%: 5; Value1: Unknown; VDC_V: 25; Value2: 25V; TaMin_C: -55; TaMax_C: 125; SizeArea_mm2: 0.5; SizeAreaWB_mm2: 3; SizeX_mm: 1; SizeZ_mm: 0.6; AEC Category: Q200
C364 C366 C376 C378 = CGA6P1X7R1C226M250AC: CAP, CERM, 22 µF, 16 V, +/- 20%, X7R, AEC-Q200 Grade 1, 1210; Manufacturer: TDK; Polarized: N; CompType: Capacitor; Value: 22uF; U/M: EA; Cap_F: 0.000022; Tolerance_%: 20; ESR_ohm: 0.002582; Value1: 0.002582 ohm; VDC_V: 16; Value2: 16V; IRMS_A: 4.57562; TaMin_C: -55; TaMax_C: 125; SizeArea_mm2: 8; SizeAreaWB_mm2: 14.7; SizeX_mm: 3.2; SizeY_mm: 2.5; SizeZ_mm: 2.8; AEC Category: Q200; AEC Qualified: Y; AEC Grade: 1
C401 = C3225X7S1H106K250AB: CAP, CERM, 10 µF, 50 V, +/- 10%, X7S, 1210; Manufacturer: TDK; Polarized: N; CompType: Capacitor; Value: 10uF; U/M: EA; Cap_F: 0.00001; Tolerance_%: 10; ESR_ohm: 0.002827; Value1: 0.002827 ohm; VDC_V: 50; IRMS_A: 4.37286; TaMin_C: -55; TaMax_C: 125; SizeArea_mm2: 8; SizeAreaWB_mm2: 14.7; SizeX_mm: 3.2; SizeY_mm: 2.5; SizeZ_mm: 2.8; AEC Category: Q200
C402 = C1608X5R1H104K080AA: CAP, CERM, 0.1 µF, 50 V, +/- 10%, X5R, 0603; Manufacturer: TDK; Polarized: N; CompType: Capacitor; Value: 0.1uF; U/M: EA; Cap_F: 0.0000001; Tolerance_%: 10; ESR_ohm: 0.0296; Value1: 0.0296 ohm; VDC_V: 50; IRMS_A: 0.97199; TaMin_C: -55; TaMax_C: 85; SizeArea_mm2: 1.28; SizeAreaWB_mm2: 4.68; SizeX_mm: 1.6; SizeY_mm: 0.8; SizeZ_mm: 1; AEC Category: Q200
C403 = GRM188R61E475KE11D: CAP, CERM, 4.7 µF, 25 V, +/- 10%, X5R, 0603; Manufacturer: MuRata; Polarized: N; CompType: Capacitor; Value: 4.7uF; U/M: EA; Cap_F: 0.0000047; Tolerance_%: 10; Value1: Unknown; VDC_V: 25; TaMin_C: -55; TaMax_C: 85; SizeArea_mm2: 1.28; SizeAreaWB_mm2: 4.68; SizeX_mm: 1.6; SizeY_mm: 0.8; SizeZ_mm: 1; AEC Category: Q200
C404 = C1608X5R1H474K080AB: CAP, CERM, 0.47 µF, 50 V, +/- 10%, X5R, 0603; Manufacturer: TDK; Polarized: N; CompType: Capacitor; Value: 0.47uF; U/M: EA; Cap_F: 0.00000047; Tolerance_%: 10; ESR_ohm: 0.010974; Value1: 0.010974 ohm; VDC_V: 50; IRMS_A: 1.57483; TaMin_C: -55; TaMax_C: 85; SizeArea_mm2: 1.28; SizeAreaWB_mm2: 4.68; SizeX_mm: 1.6; SizeY_mm: 0.8; SizeZ_mm: 1; AEC Category: Q200
C405 = C1608X7R1V105K080AC: CAP, CERM, 1 µF, 35 V, +/- 10%, X7R, 0603; Manufacturer: TDK; Polarized: N; CompType: Capacitor; Value: 1uF; U/M: EA; Cap_F: 0.000001; Tolerance_%: 10; Value1: Unknown; VDC_V: 35; Value2: 35V; TaMin_C: -55; TaMax_C: 125; SizeArea_mm2: 1.28; SizeAreaWB_mm2: 4.68; SizeX_mm: 1.6; SizeY_mm: 0.8; SizeZ_mm: 1; AEC Category: Q200
C406 = C3216X5R1V226M160AC: CAP, CERM, 22 µF, 35 V, +/- 20%, X5R, 1206; Manufacturer: TDK; Polarized: N; CompType: Capacitor; Value: 22uF; U/M: EA; Cap_F: 0.000022; Tolerance_%: 20; ESR_ohm: 0.002398; Value1: 0.002398 ohm; VDC_V: 35; IRMS_A: 4.68507; TaMin_C: -55; TaMax_C: 85; SizeArea_mm2: 5.12; SizeAreaWB_mm2: 10.92; SizeX_mm: 3.2; SizeY_mm: 1.6; SizeZ_mm: 1.8; AEC Category: Q200
C407 = C0603C223K3RACTU: CAP, CERM, 0.022 µF, 25 V, +/- 10%, X7R, 0603; Manufacturer: Kemet; Polarized: N; CompType: Capacitor; Value: 0.022uF; U/M: EA; Cap_F: 0.000000022; Tolerance_%: 10; Value1: Unknown; VDC_V: 25; Value2: 25V; TaMin_C: -55; TaMax_C: 125; SizeArea_mm2: 1.28; SizeAreaWB_mm2: 4.68; SizeX_mm: 1.6; SizeY_mm: 0.8; SizeZ_mm: 1; AEC Category: Q200
C409 = 885012006057: CAP, CERM, 100 pF, 50 V, +/- 5%, C0G/NP0, 0603; Manufacturer: Wurth Elektronik; Polarized: N; CompType: Capacitor; Value: 100pF; U/M: EA; Cap_F: 0.0000000001; Tolerance_%: 5; Value1: Unknown; VDC_V: 50; Value2: 50V; TaMin_C: -55; TaMax_C: 125; SizeArea_mm2: 1.28; SizeAreaWB_mm2: 4.68; SizeX_mm: 1.6; SizeY_mm: 0.8; SizeZ_mm: 1; AEC Category: Q200
CVCC3V CVCC5V CVCC18V = GCM188R70J225KE22D: CAP, CERM, 2.2 µF, 6.3 V, +/- 10%, X7R, AEC-Q200 Grade 1, 0603; Manufacturer: MuRata; Polarized: N; CompType: Capacitor; Value: 2.2uF; U/M: EA; Cap_F: 0.0000022; Tolerance_%: 10; Value1: Unknown; VDC_V: 6.3; Value2: 6.3V; TaMin_C: -55; TaMax_C: 125; SizeArea_mm2: 1.28; SizeAreaWB_mm2: 4.68; SizeX_mm: 1.6; SizeY_mm: 0.8; SizeZ_mm: 1; AEC Category: Q200; AEC Qualified: Y
D1 = MBRS4201T3G: Diode, Schottky, 200 V, 4 A, SMC; Manufacturer: ON Semiconductor; U/M: EA; Vf_V: 0.86; Value1: 4A; Value2: 0.86V; Io_A: 4; Vr_V: 200; TJmax_C: 150; SizeAreaWB_mm2: 83.2686; SizeArea_mm2: 50.5686; SizeX_mm: 8.13; SizeY_mm: 6.22; SizeZ_mm: 2.6; AEC Category: Q101
D14 D18 D21 D22 = 150060RS75000: LED, Red, SMD; Manufacturer: Wurth Elektronik; Type: AlInGaP; Vf_V: 2; Value2: 2V; Io_A: 0.03; Vr_V: 5; Tjmax_C: 85; Power_TotalModule: 0.072; Value1: 0.072W; Angle: 140; U/M: EA
J8 = 691213710002: Terminal Block, 2x1, Brass, TH; Manufacturer: Wurth Elektronik; SymbolCreator: a0412235; Pitch_mm: 5; Gender: Female; Row_Count: 1
J39 JTI_3.3V JTI_5V JTI_18V JTI_-18V = TMM-103-01-G-S-SM: Header, 2mm, 3x1, Gold, SMT; Manufacturer: Samtec; SymbolCreator: a0799628; Pitch_mm: 2; Gender: Male; Shrouded: N; Row_Count: 1; Current_A: 3.2; Voltage_V: 500; Cert_CSA: Y
JPRI_-18V JSI_3.3V JSI_5V JSI_18V = 61300211121: Header, 2.54 mm, 2x1, Gold, TH; Manufacturer: Wurth Elektronik; SymbolCreator: a0412235
L4 L5 L16-L19 = MPZ2012S601A: Ferrite Bead, 600 ohm @ 100MHz, 2A, 0805; Manufacturer: TDK; Imax_A: 2; DCR_ohm: 0.1; Value1: 0.1 ohm; ZTyp@100MHz_Ohm: 600
L20 L22 L24 = NR3015T3R3M: Inductor, Wirewound, Ferrite, 3.3 µH, 1.21 A, 0.096 ohm, AEC-Q200 Grade 2, SMD; Manufacturer: Taiyo Yuden; Value: 3.3uH; Imax_A: 1.21; DCR_ohm: 0.096; Value2: 1.21A; Ind_H: 3.3E-6; Irms: 1.23A @ 40C rise; Isat: 1.21A @ 30% inductance drop; SizeAreaWB_mm2: 16; SizeArea_mm2: 9; SizeX_mm: 3; SizeZ_mm: 1.5; AEC Category: Q200; AEC Qualified: Y; AEC Grade: 2
L21 L23 L25 = 744025006: Inductor, Shielded Drum Core, Ferrite, 6.8 µH, 1.1 A, 0.142 ohm, SMD; Manufacturer: Wurth Elektronik; Value: 6.8uH; Ind_H: 6.8E-6; Imax_A: 1.1; Irms: 1.1A @ 40C rise; Isat: 1.3A @ 35% inductance drop; DCR_ohm: 0.142; Value2: 1.1A; SizeAreaWB_mm2: 14.44; SizeArea_mm2: 7.84; SizeX_mm: 2.8; SizeZ_mm: 3; AEC Category: Q200
L401 = 744031680: Inductor, Shielded Drum Core, Metal Composite, 68 µH, 0.22 A, 1.15 ohm, SMD; Manufacturer: Wurth Elektronik; Value: 68uH; Ind_H: 68.0E-6; Imax_A: 0.22; Irms: 0.32A @ 30C rise; Isat: 0.22A @ 35% inductance drop; DCR_ohm: 1.15; Value2: 0.22A; SizeAreaWB_mm2: 23.04; SizeArea_mm2: 14.44; SizeX_mm: 3.8; SizeZ_mm: 1.8; AEC Category: Q200
NT1 NT2 = Net-Tie: Single point connection between nets.; SymbolCreator: codlsc
R8-R15 R17-R20 R24-R27 R30-R36 RB3 RB5 RB18 = ERJ-2GE0R00X: RES, 0, 5%, 0.063 W, 0402; Manufacturer: Panasonic; CompType: Resistor; Value: 0; Value_Code: 0000; Tolerance_%: 5; Power_W: 0.063; Value2: 0.063W; VDC_V: 50; TempCo: 600 ppm/C; EIA_Code: E24; U/M: EA; AEC Category: Q200
R21 = CRCW06030000Z0EA: RES, 0, 5%, 0.1 W, 0603; Manufacturer: Vishay-Dale; CompType: Resistor; Value: 0; Value_Code: 0000; Tolerance_%: 5; Power_W: 0.1; Value2: 0.1W; VDC_V: 75; TempCo: 200 ppm/C; SizeArea_mm2: 1.28; SizeX_mm: 1.6; SizeY_mm: 0.8; SizeZ_mm: 1; EIA_Code: E24; U/M: EA; AEC Category: Q200
R22 = RT0603DRE074R7L: RES, 4.70, 0.5%, 0.1 W, 0603; Manufacturer: Yageo America; CompType: Resistor; Value: 4.70; Res_ohm: 4.7; Value_Code: 4R70; Tolerance_%: 0.5; Power_W: 0.1; Value2: 0.1W; VDC_V: 75; TempCo: 50 ppm/C; SizeArea_mm2: 1.28; SizeX_mm: 1.6; SizeY_mm: 0.8; SizeZ_mm: 1; EIA_Code: E192; U/M: EA; AEC Category: Q200
R29 = ERJ-2GE0R00X: RES, 0, 5%, 0.063 W, 0402; Manufacturer: Panasonic; CompType: Resistor; Value: 0; Value_Code: 0000; Tolerance_%: 5; Power_W: 0.063; Value2: 0.063W; VDC_V: 50; TempCo: 600 ppm/C; SizeArea_mm2: 0.5; SizeX_mm: 1; SizeZ_mm: 0.6; EIA_Code: E24; U/M: EA; AEC Category: Q200
R43 = RG1608P-3092-B-T5: RES, 30.9 k, 0.1%, 0.1 W, 0603; Manufacturer: Susumu Co Ltd; CompType: Resistor; Value: 30.9k; Res_ohm: 30900; Value_Code: 30k9; Tolerance_%: 0.1; Value2: 0.1W; VDC_V: 75; TempCo: 25 ppm/C; SizeArea_mm2: 1.28; SizeX_mm: 1.6; SizeY_mm: 0.8; SizeZ_mm: 1; EIA_Code: E192; U/M: EA; AEC Category: Q200
R44 = RT0603BRD072K15L: RES, 2.15 k, 0.1%, 0.1 W, 0603; Manufacturer: Yageo America; CompType: Resistor; Value: 2.15k; Res_ohm: 2150; Value_Code: 2k15; Tolerance_%: 0.1; Value2: 0.1W; VDC_V: 75; TempCo: 25 ppm/C; SizeArea_mm2: 1.28; SizeX_mm: 1.6; SizeY_mm: 0.8; SizeZ_mm: 1; EIA_Code: E192; U/M: EA; AEC Category: Q200
R46 = RC0603JR-07910RL: RES, 910, 5%, 0.1 W, 0603; Manufacturer: Yageo America; CompType: Resistor; Value: 910; Value_Code: 910R; Tolerance_%: 5; Power_W: 0.1; Value2: 0.1W; VDC_V: 50; TempCo: 100 ppm/C; EIA_Code: E24; U/M: EA; AEC Category: Q200; SizeArea_mm2: 1.28; SizeX_mm: 1.6; SizeY_mm: 0.8; SizeZ_mm: 1
R47 = RT0603BRD0718KL: RES, 18.0 k, 0.1%, 0.1 W, 0603; Manufacturer: Yageo America; CompType: Resistor; Value: 18.0k; Res_ohm: 18000; Value_Code: 18k0; Tolerance_%: 0.1; Value2: 0.1W; VDC_V: 75; TempCo: 25 ppm/C; SizeArea_mm2: 1.28; SizeX_mm: 1.6; SizeY_mm: 0.8; SizeZ_mm: 1; EIA_Code: E192; U/M: EA; AEC Category: Q200
R246 R247 = RG1608P-4992-B-T5: RES, 49.9 k, 0.1%, 0.1 W, 0603; Manufacturer: Susumu Co Ltd; CompType: Resistor; Value: 49.9k; Res_ohm: 49900; Value_Code: 49k9; Tolerance_%: 0.1; Value2: 0.1W; VDC_V: 75; TempCo: 25 ppm/C; SizeArea_mm2: 1.28; SizeX_mm: 1.6; SizeY_mm: 0.8; SizeZ_mm: 1; EIA_Code: E192; U/M: EA; AEC Category: Q200
R290 = CRCW040236K0JNED: RES, 36 k, 5%, 0.063 W, 0402; Manufacturer: Vishay-Dale; CompType: Resistor; Value: 36k; Res_ohm: 36000; Value_Code: 36k0; Tolerance_%: 5; Power_W: 0.063; Value2: 0.063W; VDC_V: 50; TempCo: 200 ppm/C; SizeArea_mm2: 0.5; SizeX_mm: 1; SizeZ_mm: 0.6; EIA_Code: E24; U/M: EA; AEC Category: Q200
R291 R295 R298 = CRCW0402100KFKED: RES, 100 k, 1%, 0.063 W, 0402; Manufacturer: Vishay-Dale; CompType: Resistor; Value: 100k; Res_ohm: 100000; Tolerance_%: 1; Power_W: 0.063; Value2: 0.063W; VDC_V: 50; TempCo: 100 ppm/C; SizeArea_mm2: 0.5; SizeZ_mm: 0.6; EIA_Code: E96; U/M: EA; AEC Category: Q200
R294 = CMP-0016780-3: RES, 20.5 k, 1%, 0.25 W, AEC-Q200 Grade 0, 1206; Manufacturer: Vishay-Dale; PartNumber: CRCW120620K5FKEA; Power_W: 250mW; TempCo: 100 ppm/C; Value_Code: 20k5; Value: 20.5k; EIA_Code: E96; SizeX_mm: 3.2; SizeY_mm: 1.6; SizeZ_mm: 1.35; Value2: 0.25W; SizeArea_mm2: 5.12; AEC Qualified: Y; VDC_V: 200V; AEC Category: Q200; AEC Grade: 0
R297 = PCF0402-12-5K62BT1: RES, 5.62 k, 0.1%, 0.063 W, 0402; Manufacturer: TT Electronics/IRC; CompType: Resistor; Value: 5.62k; Res_ohm: 5620; Value_Code: 5k62; Tolerance_%: 0.1; Power_W: 0.063; Value2: 0.063W; VDC_V: 25; TempCo: 10 ppm/C; SizeArea_mm2: 0.5; SizeX_mm: 1; SizeZ_mm: 0.6; EIA_Code: E192; U/M: EA; AEC Category: Q200; AEC Qualified: N
R401 = RT0603BRD0758K3L: RES, 58.3 k, 0.1%, 0.1 W, 0603; Manufacturer: Yageo America; CompType: Resistor; Value: 58.3k; Res_ohm: 58300; Value_Code: 58k3; Tolerance_%: 0.1; Value2: 0.1W; VDC_V: 75; TempCo: 25 ppm/C; SizeArea_mm2: 1.28; SizeX_mm: 1.6; SizeY_mm: 0.8; SizeZ_mm: 1; EIA_Code: E192; U/M: EA; AEC Category: Q200
R402 = RC0603FR-071ML: RES, 1.00 M, 1%, 0.1 W, 0603; Manufacturer: Yageo America; CompType: Resistor; Value: 1.00Meg; Res_ohm: 1000000; Value_Code: 1M00; Tolerance_%: 1; Power_W: 0.1; Value2: 0.1W; VDC_V: 150; TempCo: 200 ppm/C; SizeArea_mm2: 1.28; SizeX_mm: 1.6; SizeY_mm: 0.8; EIA_Code: E96; U/M: EA; AEC Category: Q200
R404 = CRCW060380K6FKEA: RES, 80.6 k, 1%, 0.1 W, 0603; Manufacturer: Vishay-Dale; CompType: Resistor; Value: 80.6k; Res_ohm: 80600; Value_Code: 80k6; Tolerance_%: 1; Power_W: 0.1; Value2: 0.1W; VDC_V: 75; TempCo: 100 ppm/C; SizeArea_mm2: 1.28; SizeX_mm: 1.6; SizeY_mm: 0.8; EIA_Code: E96; U/M: EA; AEC Category: Q200
RES3V RES5V RES18V = RG1608P-104-B-T5: RES, 100 k, 0.1%, 0.1 W, 0603; Manufacturer: Susumu Co Ltd; CompType: Resistor; Value: 100k; Res_ohm: 100000; Tolerance_%: 0.1; Value2: 0.1W; VDC_V: 75; TempCo: 25 ppm/C; SizeArea_mm2: 1.28; SizeX_mm: 1.6; SizeY_mm: 0.8; SizeZ_mm: 1; EIA_Code: E192; U/M: EA; AEC Category: Q200
TPGND TPPGOOD = PogoPad: Pad for Pogo Pin Connector; SymbolCreator: codlsc
U3P8V U5P5V U18P5V = LMS3635MQRNLRQ1: 3.5A Synchronous Buck Regulator for Automotive Applications, RNL0022A (VQFN-HR-22); Alternate PartNumber: LMS3635MQRNLTQ1; Manufacturer: Texas Instruments; SymbolCreator: Altium; SizeArea_mm2: 20; SizeAreaWB_mm2: 42; SizeX_mm: 4; SizeY_mm: 5; SizeZ_mm: 0.9; CompType: IC; U/M: EA
U6-U8 = TPS7A4700RGWR: 36-V, 1-A, 4.17-μVRMS, RF LDO Voltage Regulator, RGW0020A; Alternate PartNumber: TPS7A4700RGWT; Manufacturer: Texas Instruments; SymbolCreator: a0412235; CompType: IC; U/M: EA
U10 = LM7705MM/NOPB: Low Noise Negative Bias Generator, 8-pin Mini SOIC, Pb-Free; Manufacturer: Texas Instruments; PackageTopMarking: ZXTT*F26A; PowerWise: N; CompType: OtherParts
U11 = TPS7A3001MDGNTEP: Single Output High PSRR LDO, 200 mA, Adjustable -1.18 to -33 V Output, -3 to -36 V Input, with Ultra-Low Noise, 8-pin MSOP (DGN), -55 to 125 degC, Green (RoHS & no Sb/Br); Manufacturer: Texas Instruments; Alternate PartNumber: Equivalent; Accuracy(%): 1.5; Iout(Max)(A): 0.2; Iq(Typ)(mA): 0.05; SubFamily: Single Channel LDO; Vdo(Typ)(mV): 216
U401 = LM46001PWPR: SIMPLE SWITCHER 3.5 V to 60 V 1 A Synchronous Step-Down Voltage Converter, PWP0016G (TSSOP-16); Alternate PartNumber: LM46001PWPT; Manufacturer: Texas Instruments; SymbolCreator: a0411947; SizeArea_mm2: 32; SizeAreaWB_mm2: 58.8; SizeX_mm: 6.4; SizeY_mm: 5; SizeZ_mm: 1.2; CompType: IC; U/M: EA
